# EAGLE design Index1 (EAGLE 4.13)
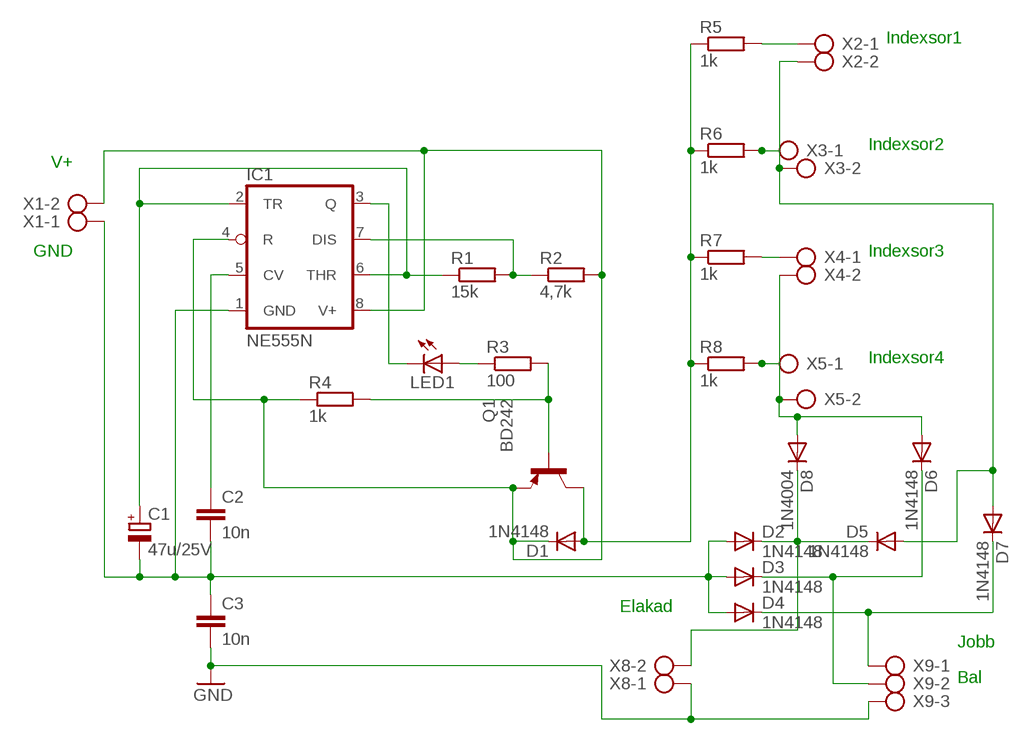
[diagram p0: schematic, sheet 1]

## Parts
C1  47u/25V  CPOL-EUE5-6  [E5-6]
C2  10n  C-EU050-025X075  [C050-025X075]
C3  10n  C-EU050-025X075  [C050-025X075]
D1  1N4148  [DO35-10]
D2  1N4148  [DO35-10]
D3  1N4148  [DO35-10]
D4  1N4148  [DO35-10]
D5  1N4148  [DO35-10]
D6  1N4148  [DO35-10]
D7  1N4148  [DO35-10]
D8  1N4004  [DO41-10]
IC1  NE555N  [DIL08]
LED1  LED5MM  [LED5MM]
Q1  BD242  [TO220]
R1  15k  R-EU_0207/10  [0207/10]
R2  4,7k  R-EU_0207/10  [0207/10]
R3  100  R-EU_0207/10  [0207/10]
R4  1k  R-EU_0207/10  [0207/10]
R5  1k  R-EU_0207/10  [0207/10]
R6  1k  R-EU_0207/10  [0207/10]
R7  1k  R-EU_0207/10  [0207/10]
R8  1k  R-EU_0207/10  [0207/10]
X1  AK500/2  [AK500/2]
X2  AK500/2  [AK500/2]
X3  AK500/2  [AK500/2]
X4  AK500/2  [AK500/2]
X5  AK500/2  [AK500/2]
X8  AK500/2  [AK500/2]
X9  AK500/3  [AK500/3]

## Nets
GND: C3.2 X8.1 X9.3
N$1: C1.- C2.2 C3.1 D2.A D3.A D4.A IC1.1(GND) X1.1
N$2: D1.A Q1.2(C) R5.1 R6.1 R7.1 R8.1
N$3: C1.+ IC1.2(TR) IC1.6(THR) R1.1
N$4: D4.C D7.C X9.1
N$5: R5.2 X2.1
N$6: IC1.7(DIS) R1.2 R2.1
N$7: R6.2 X3.1
N$8: IC1.3(Q) LED1.K(C)
N$9: LED1.A R3.1
N$10: D1.C IC1.4(R) IC1.8(V+) Q1.3(E) R2.2 R4.1 X1.2
N$11: Q1.1(B) R3.2 R4.2
N$12: R7.2 X4.1
N$13: R8.2 X5.1
N$14: D5.A D7.A X2.2 X3.2
N$15: D6.A D8.A X4.2 X5.2
N$16: C2.1 IC1.5(CV)
N$19: D2.C D5.C D8.C X8.2
N$21: D3.C D6.C X9.2

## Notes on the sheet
- Indexsor1
- Indexsor2
- V+
- GND | Indexsor3
- Indexsor4
- Elakad
- Jobb
- Bal

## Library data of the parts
C1 = rcl:CPOL-EU: POLARIZED CAPACITOR, European symbol
C2 C3 = rcl:C-EU: CAPACITOR, European symbol
D1-D7 = diode:1N4148: DIODE
D8 = diode:1N4004: DIODE
IC1 = linear:*555: TIMER
LED1 = led:LED: LED
Q1 = transistor-pnp:BD242: PNP Transistor
R1-R8 = rcl:R-EU_: RESISTOR, European symbol
X1-X5 X8 = con-ptr500:AK500/2: CONNECTOR
X9 = con-ptr500:AK500/3: CONNECTOR

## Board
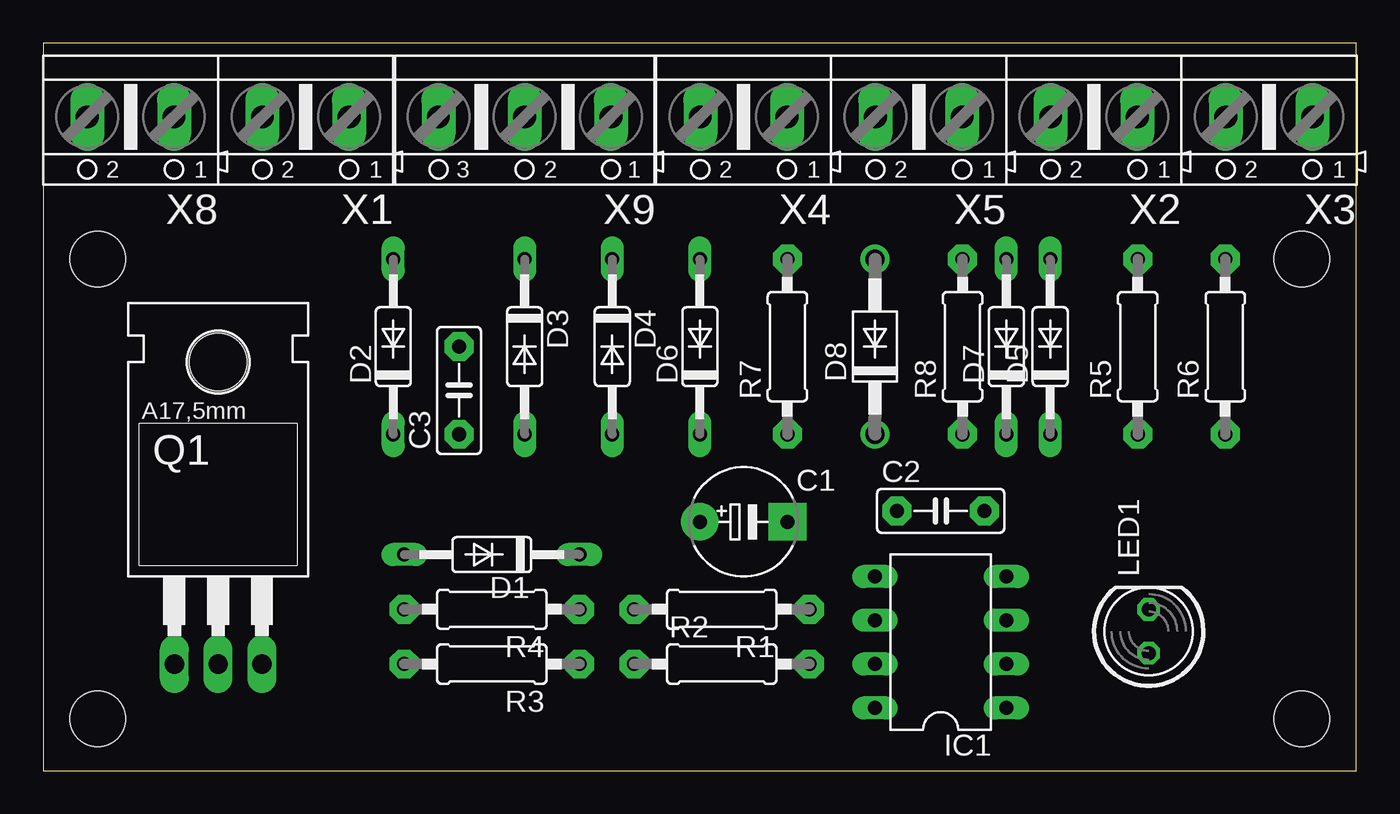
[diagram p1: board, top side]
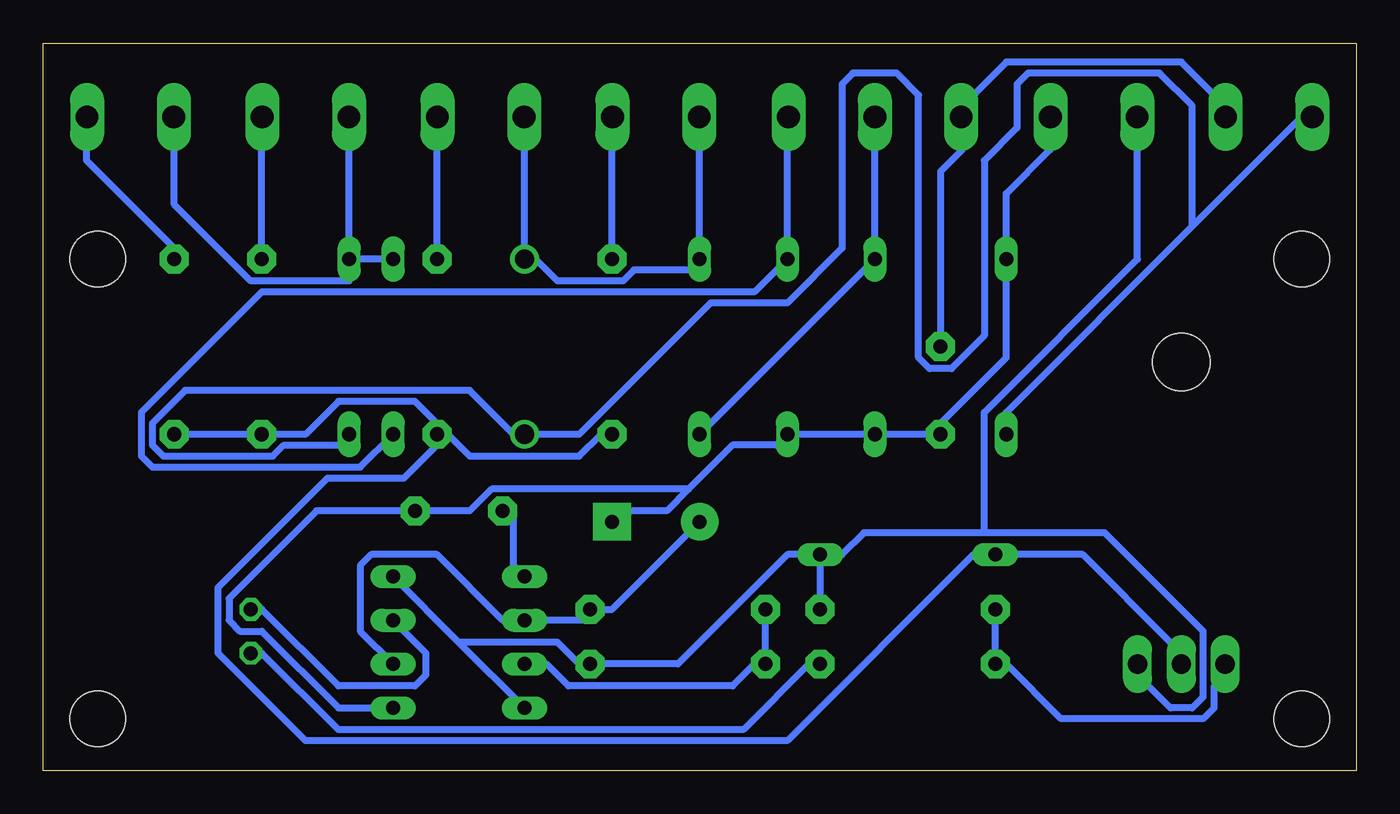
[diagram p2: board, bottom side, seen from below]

Size 76.18 x 42.22 mm. Coordinates in mm from the lower left corner, seen from the top.
Outline: 0,0 76.18,0 76.18,42.22 0,42.22 0,0
Copper layers (1*16): Top 0.035mm / dielectric 1.5mm / Bottom 0.035mm
Design rules "default": minimum track width 16mil, minimum drill 24mil, track to track 8mil, track to pad 8mil, pad to pad 8mil, via to via 8mil, smd to smd 8mil, copper to edge 40mil, drill to drill 8mil, minimum pad ring 10mil, minimum via ring 8mil, stop-mask expansion 4mil, vias tented up to drill 0mil, thermal gap 10mil
Holes 3.2 mm at 3.17,29.68 73.02,3.01 73.02,29.68 3.17,3.01

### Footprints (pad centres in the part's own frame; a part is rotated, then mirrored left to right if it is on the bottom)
E5-6 = drill 0.813 pad 2.184 round: + -2.54,0 | drill 0.813 pad 2.184 square: - 2.54,0
C050-025X075 = drill 0.813 pad 1.676 octagon: 1 -2.54,0; 2 2.54,0
DO35-10 = drill 0.813 long: A 5.08,0; C -5.08,0
DO41-10 = drill 1.118 round: A 5.08,0; C -5.08,0
DIL08 = drill 0.813 long: 1 -3.81,-3.81; 2 -1.27,-3.81; 3 1.27,-3.81; 4 3.81,-3.81; 5 3.81,3.81; 6 1.27,3.81; 7 -1.27,3.81; 8 -3.81,3.81
LED5MM = drill 0.813 octagon: A -1.27,0; K 1.27,0
TO220 = drill 1.118 long: 1 -2.54,-6.35; 2 0,-6.35; 3 2.54,-6.35 | hole 3.302: 0,11.176
0207/10 = drill 0.813 pad 1.676 octagon: 1 -5.08,0; 2 5.08,0
AK500/2 = drill 1.321 long: 1 -2.515,0; 2 2.515,0
AK500/3 = drill 1.321 long: 1 -5.004,0; 2 0,0; 3 5.004,0

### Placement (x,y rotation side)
C1  40.63,14.44 0 top
C2  52.06,15.08 0 top
C3  24.12,22.06 90 top
D1  26.03,12.53 180 top
D2  20.32,24.6 90 top
D3  27.94,24.6 270 top
D4  33.02,24.6 270 top
D5  58.41,24.6 90 top
D6  38.09,24.6 90 top
D7  55.88,24.6 90 top
D8  48.25,24.6 90 top
IC1  52.06,7.45 90 top
LED1  64.13,8.09 90 top
Q1  10.16,12.53 0 top
R1  39.36,9.36 180 top
R2  39.36,6.18 0 top
R3  26.03,6.18 180 top
R4  26.03,9.36 180 top
R5  63.49,24.6 90 top
R6  68.58,24.6 90 top
R7  43.17,24.6 90 top
R8  53.34,24.6 90 top
X1  15.23,37.94 180 top
X2  60.95,37.94 180 top
X3  71.11,37.94 180 top
X4  40.63,37.94 180 top
X5  50.79,37.94 180 top
X8  5.08,37.94 180 top
X9  27.94,37.94 180 top

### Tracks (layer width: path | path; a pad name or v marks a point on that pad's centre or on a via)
GND
  Bottom 0.406: C3.2 24.12,34.76 22.86,36.03 X9.3 22.22,39.2 20.32,41.11 10.16,41.11 8.25,39.2 X8.1
N$1
  Bottom 0.406: IC1.1 59.05,3.64 63.49,8.09 64.77,8.09 65.4,8.72 65.4,9.99 60.32,15.08 C2.2 51.43,15.08 50.16,16.34 38.73,16.34 | X1.1 17.78,36.03 20.32,33.49 D2.A 20.32,23.97 24.12,20.16 C3.1 D3.A D4.A 33.65,18.88 36.19,18.88 38.73,16.34 | 38.73,16.34 40,15.08 42.54,15.08 C1.-
N$2
  Bottom 0.406: Q1.2 10.79,7.45 15.87,12.53 D1.A 22.22,12.53 33.02,1.74 60.95,1.74 66.03,6.82 66.03,10.63 59.68,16.98 55.24,16.98 53.34,18.88 R8.1 | R6.1 R5.1 60.95,19.52 59.05,21.42 54.6,21.42 53.34,20.16 R8.1 | R7.1 43.81,19.52 45.08,18.25 51.43,18.25 52.7,19.52 R8.1
N$3
  Bottom 0.406: IC1.2 57.78,8.09 57.78,11.9 57.14,12.53 53.34,12.53 49.52,8.72 IC1.6 44.45,8.72 R1.1 43.17,9.36 C1.+
N$4
  Bottom 0.406: X9.1 33.02,36.03 D4.C 34.92,27.77 63.49,27.77 70.48,20.79 70.48,18.25 69.84,17.61 57.78,17.61 D7.C
N$5
  Bottom 0.406: R5.2 63.49,36.03 X2.1
N$6
  Bottom 0.406: IC1.7 46.98,6.18 45.71,4.91 36.19,4.91 34.92,6.18 R2.1 R1.2
N$7
  Bottom 0.406: R6.2 68.58,30.31 73.66,35.39 73.66,36.03 X3.1
N$8
  Bottom 0.406: IC1.3 53.97,6.82 53.97,5.55 54.6,4.91 59.05,4.91 63.49,9.36 LED1.K
N$9
  Bottom 0.406: LED1.A 63.49,6.82 59.05,2.38 35.55,2.38 31.75,6.18 R3.1
N$10
  Bottom 0.406: 52.06,7.45 IC1.8 | 52.06,7.45 IC1.4 | 52.06,7.45 46.35,7.45 45.08,6.18 R2.2 39.36,6.18 33.02,12.53 D1.C | D1.C R4.1 | 21.59,13.8 28.57,13.8 29.84,12.53 D1.C | 21.59,13.8 14.6,13.8 8.89,8.09 8.89,4.28 9.52,3.64 10.79,3.64 12.06,4.91 Q1.3 | 21.59,13.8 21.59,20.79 12.7,29.68 12.7,36.03 X1.2
N$11
  Bottom 0.406: Q1.1 8.25,4.91 8.25,3.64 8.89,3.01 17.14,3.01 20.32,6.18 R3.2 R4.2
N$12
  Bottom 0.406: R7.2 43.17,36.03 X4.1
N$13
  Bottom 0.406: R8.2 53.34,36.03 X5.1
N$14
  Bottom 0.406: D7.A D5.A | D5.A 58.41,36.03 X2.2 | X3.2 68.58,36.03 68.58,32.86 64.13,28.41 58.41,28.41 D5.A
N$15
  Bottom 0.406: X4.2 38.09,36.03 D6.A 38.73,29.05 41.91,29.05 42.54,28.41 46.35,28.41 47.62,29.68 D8.A 48.25,36.03 X5.2
N$16
  Bottom 0.406: IC1.5 48.89,11.9 48.89,15.08 C2.1
N$19
  Bottom 0.406: D5.C 59.05,18.88 62.22,18.88 62.86,18.25 69.21,18.25 69.84,18.88 69.84,20.16 67.94,22.06 51.43,22.06 48.89,19.52 D8.C 45.08,19.52 37.46,27.14 33.02,27.14 29.84,30.31 29.84,39.84 29.21,40.47 26.67,40.47 25.39,39.2 25.39,23.97 24.76,23.33 23.49,23.33 21.59,25.23 21.59,35.39 19.68,37.3 19.68,39.84 19.05,40.47 11.43,40.47 9.52,38.57 9.52,31.58 | 9.52,31.58 3.17,37.94 X8.2 | 9.52,31.58 20.32,20.79 D2.C
N$21
  Bottom 0.406: X9.2 D3.C D6.C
